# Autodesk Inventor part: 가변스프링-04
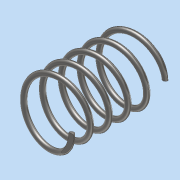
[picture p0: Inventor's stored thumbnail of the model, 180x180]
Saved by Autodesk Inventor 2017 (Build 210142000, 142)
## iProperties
Part Number: 가변스프링-04
Material: 강철, 연강
Document SubType Name: Modeling
Designer: MRC
Density: 7.85 g/cm^3
Appearance: 반연마
Mass: 8.42301 g
Surface Area: 21.7219 cm^2
Volume: 1.07299 cm^3
Author: MRC
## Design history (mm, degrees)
sketch "스케치1"
  geometry: L1 (0, 0)-(11, 0); L2 (11, 0)-(11, 36.411); L3 (11, 36.411)-(0, 36.411); L4 (0, 36.411)-(0, 0); C1 r 1 at (11, 0)
  constraints: 8 end point, 2 parallel, 1 centre point, 1 coincident, 1 horizontal, 1 perpendicular
  dimensions: "d0" = 36.4112 distance of L3.end L1.start (derived); "d1" = 22 diameter of L2 L4; "d2" = 2 diameter of C1
feature "코일1" sketch "스케치1" pitch "d3" = 10; turns "d5" = 5; dims "d4" = 36.4112 (= d0), "d6" = 0, angle "d7" = 90 deg, angle "d8" = 90 deg, "d9" = 0, "d10" = 0
sketch "스케치2"
  geometry: L1 (36.411, 17.383)-(0, 17.383); L2 (0, 17.383)-(0, -17.383); L3 (0, -17.383)-(36.411, -17.383); L4 (36.411, -17.383)-(36.411, 17.383); 2 further points
  constraints: 8 end point, 2 parallel, 1 coincident, 1 horizontal, 1 midpoint, 1 perpendicular
  dimensions: "d11" = 36.4112 distance of L2.end L3.end (= d0); "d12" = 34.76604 distance of L3.end L1.start
extrude "돌출1" sketch "스케치2" stored distance "d13" = 47.75; taper "d14" = 0 deg
node "솔리드1"
